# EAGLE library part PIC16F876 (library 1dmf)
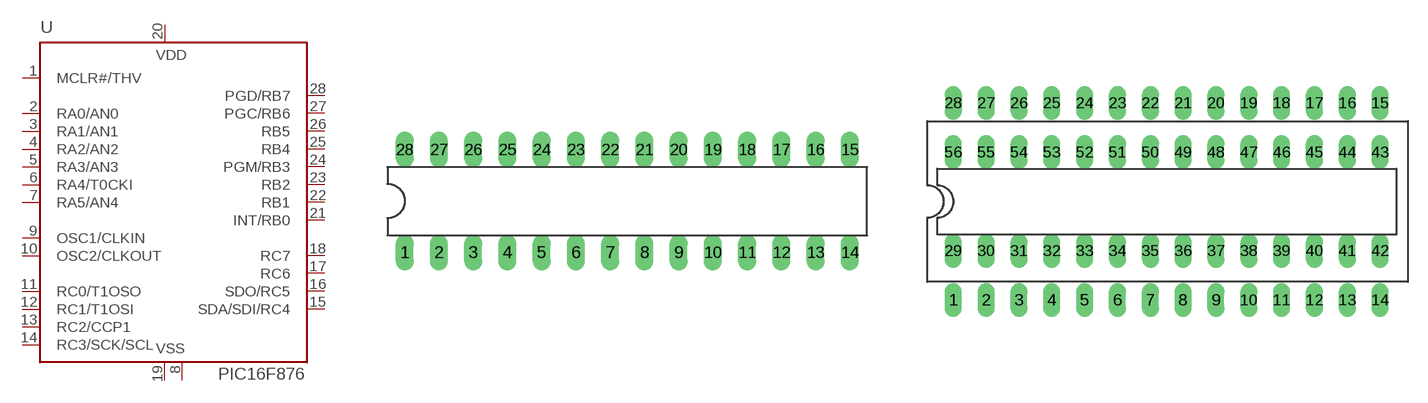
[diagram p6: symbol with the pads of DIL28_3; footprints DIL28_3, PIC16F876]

Designator prefix -

## PIC16F876  [DIL28_3]
1  MCLR#/THV  in
2  RA0/AN0
3  RA1/AN1
4  RA2/AN2
5  RA3/AN3
6  RA4/T0CKI
7  RA5/AN4
8  VSS  pwr
9  OSC1/CLKIN  in
10  OSC2/CLKOUT  out
11  RC0/T1OSO
12  RC1/T1OSI
13  RC2/CCP1
14  RC3/SCK/SCL
15  SDA/SDI/RC4
16  SDO/RC5
17  RC6
18  RC7
19  VSS  pwr
20  VDD  pwr
21  INT/RB0
22  RB1
23  RB2
24  PGM/RB3
25  RB4
26  RB5
27  PGC/RB6
28  PGD/RB7

## PIC16F876ZIF  [PIC16F876]
Pads as for DIL28_3

## PIC16F876DIL28_3_SOCKET  [DIL28_3_SOCKET]
Pads as for DIL28_3

## Footprint DIL28_3 (pad centres in mm)
drill 0.813 long: 1 -16.51,-3.81; 2 -13.97,-3.81; 3 -11.43,-3.81; 4 -8.89,-3.81; 5 -6.35,-3.81; 6 -3.81,-3.81; 7 -1.27,-3.81; 8 1.27,-3.81; 9 3.81,-3.81; 10 6.35,-3.81; 11 8.89,-3.81; 12 11.43,-3.81; 13 13.97,-3.81; 14 16.51,-3.81; 15 16.51,3.81; 16 13.97,3.81; 17 11.43,3.81; 18 8.89,3.81; 19 6.35,3.81; 20 3.81,3.81; 21 1.27,3.81; 22 -1.27,3.81; 23 -3.81,3.81; 24 -6.35,3.81; 25 -8.89,3.81; 26 -11.43,3.81; 27 -13.97,3.81; 28 -16.51,3.81

## Footprint PIC16F876 (pad centres in mm)
drill 0.813 long: 1 -15.24,-7.62; 2 -12.7,-7.62; 3 -10.16,-7.62; 4 -7.62,-7.62; 5 -5.08,-7.62; 6 -2.54,-7.62; 7 0,-7.62; 8 2.54,-7.62; 9 5.08,-7.62; 10 7.62,-7.62; 11 10.16,-7.62; 12 12.7,-7.62; 13 15.24,-7.62; 14 17.78,-7.62; 15 17.78,7.62; 16 15.24,7.62; 17 12.7,7.62; 18 10.16,7.62; 19 7.62,7.62; 20 5.08,7.62; 21 2.54,7.62; 22 0,7.62; 23 -2.54,7.62; 24 -5.08,7.62; 25 -7.62,7.62; 26 -10.16,7.62; 27 -12.7,7.62; 28 -15.24,7.62; 29 -15.24,-3.81; 30 -12.7,-3.81; 31 -10.16,-3.81; 32 -7.62,-3.81; 33 -5.08,-3.81; 34 -2.54,-3.81; 35 0,-3.81; 36 2.54,-3.81; 37 5.08,-3.81; 38 7.62,-3.81; 39 10.16,-3.81; 40 12.7,-3.81; 41 15.24,-3.81; 42 17.78,-3.81; 43 17.78,3.81; 44 15.24,3.81; 45 12.7,3.81; 46 10.16,3.81; 47 7.62,3.81; 48 5.08,3.81; 49 2.54,3.81; 50 0,3.81; 51 -2.54,3.81; 52 -5.08,3.81; 53 -7.62,3.81; 54 -10.16,3.81; 55 -12.7,3.81; 56 -15.24,3.81

## Footprint DIL28_3_SOCKET (pad centres in mm)
drill 0.813 long: 1 -15.24,-3.81; 2 -12.7,-3.81; 3 -10.16,-3.81; 4 -7.62,-3.81; 5 -5.08,-3.81; 6 -2.54,-3.81; 7 0,-3.81; 8 2.54,-3.81; 9 5.08,-3.81; 10 7.62,-3.81; 11 10.16,-3.81; 12 12.7,-3.81; 13 15.24,-3.81; 14 17.78,-3.81; 15 17.78,3.81; 16 15.24,3.81; 17 12.7,3.81; 18 10.16,3.81; 19 7.62,3.81; 20 5.08,3.81; 21 2.54,3.81; 22 0,3.81; 23 -2.54,3.81; 24 -5.08,3.81; 25 -7.62,3.81; 26 -10.16,3.81; 27 -12.7,3.81; 28 -15.24,3.81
